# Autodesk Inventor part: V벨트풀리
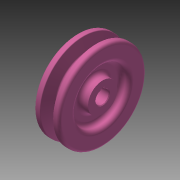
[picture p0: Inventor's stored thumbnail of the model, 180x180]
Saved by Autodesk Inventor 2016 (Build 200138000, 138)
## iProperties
Created: 2015-11
Part Number: V벨트풀리
Material: 강철, 탄소
Document SubType Name: Modeling
Designer: mduedu
Density: 1 g/cm^3
Appearance: 분홍색
Author: mduedu
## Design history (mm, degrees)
sketch "스케치1"
  geometry: L1 (-9.5, 0)-(9.5, 0); L2 (0, 0)-(0, 32.7); L3 (-4.825, 32.7)-(-9.5, 32.7); L4 (-9.5, 32.7)-(-9.5, 0); L5 (0, 23.7)-(-2.074, 23.7); L6 (-2.074, 23.7)-(-4.825, 32.7); L7 (4.825, 32.7)-(9.5, 32.7); L8 (9.5, 32.7)-(9.5, 0); L9 (0, 23.7)-(2.074, 23.7); L10 (2.074, 23.7)-(4.825, 32.7); L11 (-9.5, 30)-(9.5, 30); 3 further points
  constraints: 22 end point, 7 point on line, 4 perpendicular, 3 symmetric about line, 1 coincident, 1 horizontal, 1 horizontal alignment, 1 midpoint, 1 vertical
  dimensions: "d0" = 19 distance of L1.start L1.end; "d2" = 65.4 diameter of L2.end L1 (derived); "d3" = 34 deg angle of L10 L6; "d4" = 6.3 distance between parallel lines of L11 L9; "d5" = 2.7 distance between parallel lines of L7 L11; "d6" = 8 distance of point (4, 30) point (-4, 30); "d7" = 60 diameter of L11 L1
revolve "회전1" sketch "스케치1" stored, may be unused: angle "d8" = 90 deg
sketch "스케치2"
  geometry: C1 r 20 at (0, 0); C2 r 11 at (0, 0); 1 further point
  constraints: 2 centre point, 2 coincident
  dimensions: "d9" = 40 diameter of C1; "d10" = 22 diameter of C2
extrude "돌출1" cut sketch "스케치2" distance "d11" = 6; taper "d12" = 0 deg
fillet "모깎기1" dims "d13" = 3
fillet "모깎기2" dims "d14" = 3
fillet "모깎기3" dims "d15" = 1, "d16" = 0.5, "d17" = 2
hole "구멍1" diameter "d20" = 10; stored, may be unused: countersink angle "d24" = 90 deg, drill point angle "d26" = 118 deg; dims "d18" = 10, "d19" = 10, "d21" = 6, "d22" = 4, "d23" = 2, "d25" = 8
sketch "스케치3"
  geometry: L1 (-1.5, 0)-(1.5, 0); L2 (1.5, 0)-(1.5, 6.4); L3 (1.5, 6.4)-(-1.5, 6.4); L4 (-1.5, 6.4)-(-1.5, 0); 2 further points
  constraints: 8 end point, 2 parallel, 1 coincident, 1 horizontal, 1 midpoint, 1 perpendicular
  dimensions: "d27" = 3 distance of L2.end L3.end; "d29" = 6.4 distance of L3.end L1.start
extrude "돌출2" cut sketch "스케치3" stored distance "d30" = 6; taper "d31" = 0 deg
chamfer "모따기1" distance "d32" = 0.5; stored, may be unused: second distance "d33" = 2, angle "d34" = 45 deg
node "솔리드1"
mirror "대칭1"
